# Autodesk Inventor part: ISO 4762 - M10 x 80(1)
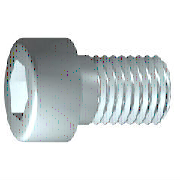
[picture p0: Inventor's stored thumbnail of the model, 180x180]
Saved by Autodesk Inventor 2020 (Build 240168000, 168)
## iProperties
Created: 2019-01
Part Number: ISO 4762 - M10 x 80(1)
Material: Nerezová ocel 440C
Description: Šroub s válcovou hlavou s vnitřním šestihranem
Document SubType Name: Modeling
Standard: ISO 4762
Designer: doma
Standard Revision: Fourth edition 2004-03-01
Standards Organization: ISO
Language: cs-CZ
Size Designation: M10 x 80
Categories: <MemberInstance><Categories><Category DisplayName="Spojovací materiál" InternalName="e4da775c-781d-43d5-af7c-5136215cf5a6" Mnemonic="FSTN"><Category DisplayName
Density: 7.75 g/cm^3
Appearance: Pololeštěná
IsCustomPart: 0
Author: doma
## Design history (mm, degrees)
sketch "Náčrt1"
  geometry: L1 (-2.333, 0)-(80, 0); L2 (80, 0)-(80, 5); L3 (80, 5)-(48, 5); L4 (48, 5)-(47.08, 5); L5 (47.08, 5)-(0, 5); L6 (0, 5)-(0, 8); L7 (0, 8)-(-10, 8); L8 (-10, 8)-(-10, 4.619); L9 (-10, 4.619)-(-5, 4.619); L10 (-5, 4.619)-(-2.333, 0); L11 (-28, 0)-(98, 0) reference; L12 (0, -1.6)-(0, 9.6) reference; L13 (48, 5)-(0, 5)
  constraints: 22 end point, 6 parallel, 2 collinear, 2 perpendicular, 1 horizontal, 1 point on line
  dimensions: "d1" = 32 distance from line of L3.end L2 (= GEL); "d2" = 0.92028 distance of L4.end L3.end (computed from GAL); "d3" = 10 distance between parallel lines of L8 L6 (= KOH); "d4" = 5 distance of L8.end L9.end (= INTI); "d5" = 60 deg angle of L10 L1; "d6" = 10 diameter of L3 L1 (= GD); "d7" = 10 diameter of L5 L1 (= BDM); "d8" = 9.2376 diameter of L9 L1 (= 1.1547 x SW); "d9" = 16 diameter of L7 L1 (= KOD); "d26" = 80 distance between parallel lines of L12 L2 (= NLG)
revolve "Těleso" sketch "Náčrt1" stored, may be unused: angle "d10" = 90 deg
sketch "Náčrt2"
  geometry: L1 (0, -11.2)-(0, 11.2) reference; L2 (-11.2, 0)-(11.2, 0) reference; L3 (4.619, 0)-(2.309, -4); L4 (2.309, -4)-(-2.309, -4); L5 (-2.309, -4)-(-4.619, 0); L6 (-4.619, 0)-(-2.309, 4); L7 (-2.309, 4)-(2.309, 4); L8 (2.309, 4)-(4.619, 0); 2 further points
  constraints: 12 end point, 1 coincident, 1 horizontal alignment, 1 point on line, 12 other
extrude "Drážka" join sketch "Náčrt2" stored distance "d11" = 10; taper "d12" = 0 deg
workplane "Work Plane1"
fillet "Fillet2" dims "d30" = 0.1 (= R)
body "Solid1"
fillet "Zaoblení1" dims "d17" = 1 (= RR)
feature "Závit" dims "d13" = 32 (= GEL), "d14" = 0
chamfer "Zkosení1" distance "d15" = 0.92018 (= -0.5 x SPD + 0.5 x GD); stored, may be unused: second distance "d16" = 0.92018 (= GUL), angle "d27" = 45 deg
other parameters: "GD" = 10 [user parameter; used in 2 equation terms], "NLG" = 80 [user parameter; used in 1 equation term], "GEL" = 32 [user parameter; used in 2 equation terms], "KOD" = 16 [user parameter; used in 1 equation term], "KOH" = 10 [user parameter; used in 1 equation term], "INTI" = 5 [user parameter; used in 1 equation term], "GAL" = 0.92018 (= 0.61345 x PTC) [user parameter; used in 1 equation term], "GUL" = 0.92018 (= 0.61345 x PTC) [user parameter; used in 1 equation term], "BDM" = 10 (= NND) [user parameter; used in 1 equation term], "SW" = 8 [user parameter; used in 2 equation terms], "RR" = 1 [user parameter; used in 1 equation term], "SPD" = 8.15965 (= NND - 1.2269 x PTC) [user parameter; used in 1 equation term], "d19" = 0, "d28" = 0, "d29" = 0, "R" = 0.1 [user parameter; used in 1 equation term], "TOA" = 30 deg [user parameter], "GD1" = 8.15965 (= THREADDIA - 1.2269 x PTC) [user parameter], "FAWI" = 45 deg [user parameter], "TPU" = 6.66667 (computed from PTC) [user parameter], "PTC" = 1.5 [user parameter; used in 5 equation terms], "E0" = 9.24 (= 1.155 x SW) [user parameter]
